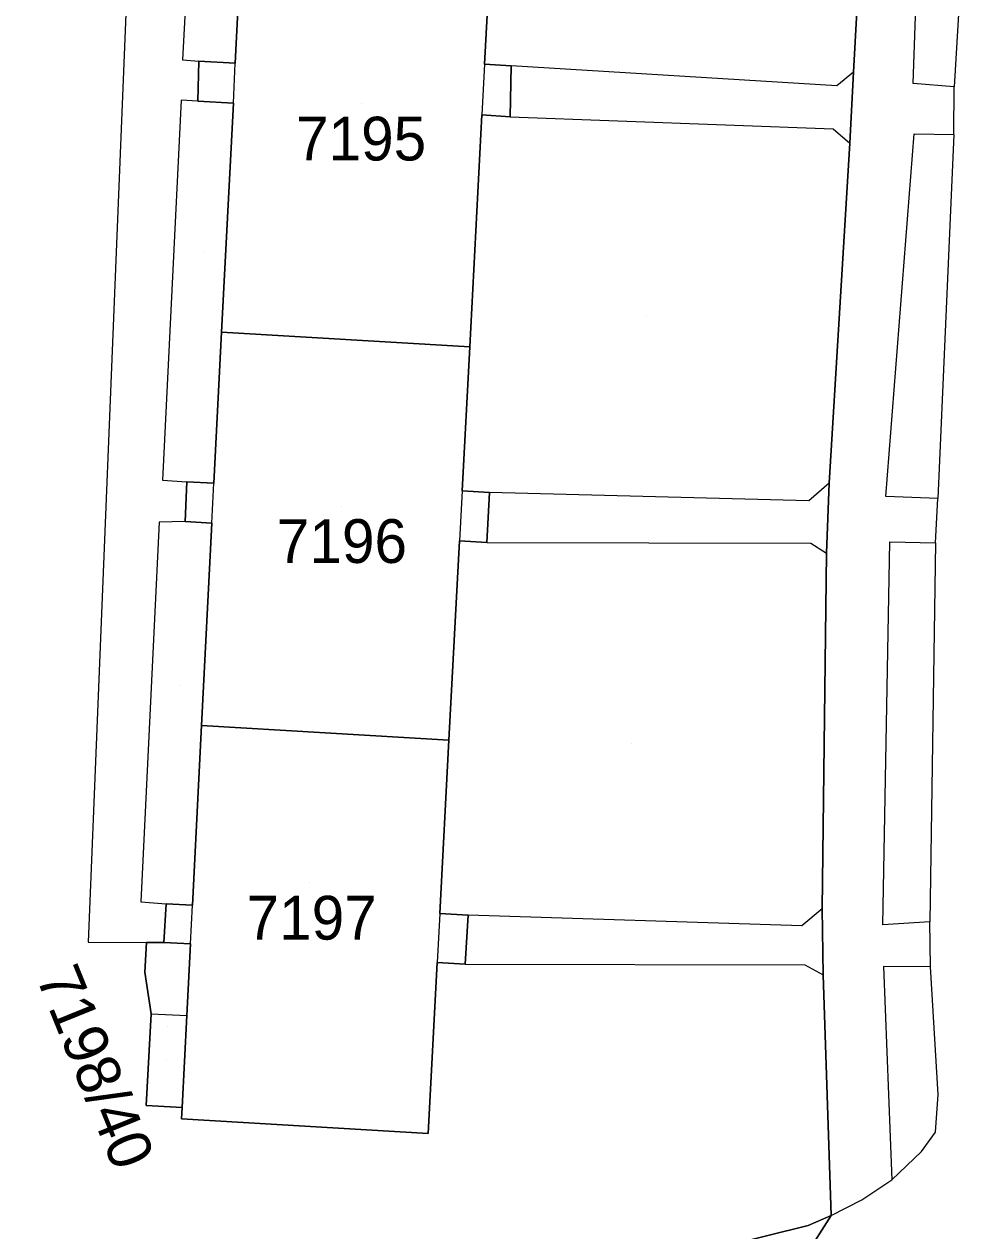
# Model space of a CAD drawing. Extents: x -266199 to -261993, y -1239047 to -1235108.
# Drawn here: x -263566.8 to -263523.4, y -1236600.9 to -1236545.7 of the extents above; entities that cross this region are included whole.
import ezdxf

# ---------------------------------------------------------------- set-up
doc = ezdxf.new("R2010")
doc.units = 0
for name, color, linetype in [('body_kn', 7, 'Continuous'), ('kladpar_druhypozemkov', 7, 'Continuous'), ('kladpar_hranice', 7, 'Continuous'), ('kladpar_parcelnecisla', 7, 'Continuous'), ('kladpar_plochy', 7, 'Continuous'), ('kladpar_sipky', 7, 'Continuous'), ('zappar_hrandruhpozemk', 7, 'Continuous')]:
    doc.layers.add(name, color=color, linetype=linetype)

msp = doc.modelspace()

# ---------------------------------------------------------------- linework, layer by layer
at = {"layer": 'body_kn'}
for p, q in [((-263559.56, -1236547.35), (-263559.56, -1236547.35)), ((-263558.81, -1236547.41), (-263558.81, -1236547.41)), ((-263557.15, -1236547.51), (-263557.15, -1236547.51)), ((-263545.76, -1236547.55), (-263545.76, -1236547.55)), ((-263545.76, -1236547.55), (-263545.76, -1236547.55)), ((-263544.54, -1236547.62), (-263544.54, -1236547.62)), ((-263528.91, -1236547.91), (-263528.91, -1236547.91)), ((-263528.91, -1236547.91), (-263528.91, -1236547.91)), ((-263529.67, -1236548.54), (-263529.67, -1236548.54)), ((-263526.18, -1236548.44), (-263526.18, -1236548.44)), ((-263526.18, -1236548.44), (-263526.18, -1236548.44)), ((-263524.3, -1236548.58), (-263524.3, -1236548.58)), ((-263559.62, -1236549.19), (-263559.62, -1236549.19)), ((-263558.86, -1236549.24), (-263558.86, -1236549.24)), ((-263558.86, -1236549.24), (-263558.86, -1236549.24)), ((-263557.24, -1236549.33), (-263557.24, -1236549.33)), ((-263557.24, -1236549.33), (-263557.24, -1236549.33)), ((-263545.88, -1236549.87), (-263545.88, -1236549.87)), ((-263544.59, -1236549.95), (-263544.59, -1236549.95)), ((-263544.59, -1236549.95), (-263544.59, -1236549.95)), ((-263529.84, -1236550.5), (-263529.84, -1236550.5)), ((-263529.07, -1236551.16), (-263529.07, -1236551.16)), ((-263526.13, -1236550.74), (-263526.13, -1236550.74)), ((-263524.32, -1236550.77), (-263524.32, -1236550.77)), ((-263524.32, -1236550.77), (-263524.32, -1236550.77)), ((-263557.78, -1236559.79), (-263557.78, -1236559.79)), ((-263557.78, -1236559.79), (-263557.78, -1236559.79)), ((-263546.44, -1236560.46), (-263546.44, -1236560.46)), ((-263546.44, -1236560.46), (-263546.44, -1236560.46)), ((-263560.47, -1236566.56), (-263560.47, -1236566.56)), ((-263559.36, -1236566.63), (-263559.36, -1236566.63)), ((-263558.13, -1236566.7), (-263558.13, -1236566.7)), ((-263546.79, -1236567.04), (-263546.79, -1236567.04)), ((-263546.79, -1236567.04), (-263546.79, -1236567.04)), ((-263545.53, -1236567.12), (-263545.53, -1236567.12)), ((-263530.01, -1236566.7), (-263530.01, -1236566.7)), ((-263530.01, -1236566.7), (-263530.01, -1236566.7)), ((-263530.95, -1236567.5), (-263530.95, -1236567.5)), ((-263527.43, -1236567.3), (-263527.43, -1236567.3)), ((-263527.43, -1236567.3), (-263527.43, -1236567.3)), ((-263525.05, -1236567.39), (-263525.05, -1236567.39)), ((-263560.63, -1236568.48), (-263560.63, -1236568.48)), ((-263559.44, -1236568.45), (-263559.44, -1236568.45)), ((-263559.44, -1236568.45), (-263559.44, -1236568.45)), ((-263558.22, -1236568.52), (-263558.22, -1236568.52)), ((-263558.22, -1236568.52), (-263558.22, -1236568.52)), ((-263546.91, -1236569.33), (-263546.91, -1236569.33)), ((-263527.24, -1236569.37), (-263527.24, -1236569.37)), ((-263545.66, -1236569.41), (-263545.66, -1236569.41)), ((-263545.66, -1236569.41), (-263545.66, -1236569.41)), ((-263530.85, -1236569.44), (-263530.85, -1236569.44)), ((-263530.13, -1236569.9), (-263530.13, -1236569.9)), ((-263525.15, -1236569.42), (-263525.15, -1236569.42)), ((-263525.15, -1236569.42), (-263525.15, -1236569.42)), ((-263558.69, -1236577.76), (-263558.69, -1236577.76)), ((-263558.69, -1236577.76), (-263558.69, -1236577.76)), ((-263547.39, -1236578.44), (-263547.39, -1236578.44)), ((-263547.39, -1236578.44), (-263547.39, -1236578.44)), ((-263561.46, -1236585.82), (-263561.46, -1236585.82)), ((-263560.31, -1236585.91), (-263560.31, -1236585.91)), ((-263559.11, -1236585.98), (-263559.11, -1236585.98)), ((-263547.81, -1236586.36), (-263547.81, -1236586.36)), ((-263547.81, -1236586.36), (-263547.81, -1236586.36)), ((-263546.51, -1236586.44), (-263546.51, -1236586.44)), ((-263530.33, -1236586.15), (-263530.33, -1236586.15)), ((-263530.33, -1236586.15), (-263530.33, -1236586.15)), ((-263531.26, -1236586.92), (-263531.26, -1236586.92)), ((-263527.56, -1236586.88), (-263527.56, -1236586.88)), ((-263527.56, -1236586.88), (-263527.56, -1236586.88)), ((-263525.42, -1236586.74), (-263525.42, -1236586.74)), ((-263563.87, -1236587.67), (-263563.87, -1236587.67)), ((-263561.2, -1236587.68), (-263561.2, -1236587.68)), ((-263561.2, -1236587.68), (-263561.2, -1236587.68)), ((-263560.41, -1236587.68), (-263560.41, -1236587.68)), ((-263559.2, -1236587.75), (-263559.2, -1236587.75)), ((-263559.2, -1236587.75), (-263559.2, -1236587.75)), ((-263547.93, -1236588.6), (-263547.93, -1236588.6)), ((-263561.29, -1236589.04), (-263561.29, -1236589.04)), ((-263546.64, -1236588.68), (-263546.64, -1236588.68)), ((-263546.64, -1236588.68), (-263546.64, -1236588.68)), ((-263531.13, -1236588.71), (-263531.13, -1236588.71)), ((-263530.29, -1236589.16), (-263530.29, -1236589.16)), ((-263527.53, -1236588.78), (-263527.53, -1236588.78)), ((-263525.39, -1236588.79), (-263525.39, -1236588.79)), ((-263525.39, -1236588.79), (-263525.39, -1236588.79)), ((-263561, -1236590.94), (-263561, -1236590.94)), ((-263561, -1236590.94), (-263561, -1236590.94)), ((-263559.37, -1236591.02), (-263559.37, -1236591.02)), ((-263525.04, -1236594.63), (-263525.04, -1236594.63)), ((-263561.22, -1236595.13), (-263561.22, -1236595.13)), ((-263559.58, -1236595.22), (-263559.58, -1236595.22)), ((-263559.61, -1236595.74), (-263559.61, -1236595.74)), ((-263525.15, -1236596.35), (-263525.15, -1236596.35)), ((-263548.34, -1236596.41), (-263548.34, -1236596.41)), ((-263548.34, -1236596.41), (-263548.34, -1236596.41)), ((-263525.8, -1236597.23), (-263525.8, -1236597.23)), ((-263527.16, -1236598.52), (-263527.16, -1236598.52)), ((-263527.16, -1236598.52), (-263527.16, -1236598.52)), ((-263528.53, -1236599.44), (-263528.53, -1236599.44)), ((-263529.92, -1236600.16), (-263529.92, -1236600.16)), ((-263529.92, -1236600.16), (-263529.92, -1236600.16)), ((-263530.98, -1236600.62), (-263530.98, -1236600.62))]:
    msp.add_line(p, q, dxfattribs=at)
at = {"layer": 'kladpar_druhypozemkov'}
for p, q in [((-263551.38, -1236549.35), (-263551.38, -1236549.35)), ((-263558.6, -1236556.16), (-263558.6, -1236556.16)), ((-263538.38, -1236559.05), (-263538.38, -1236559.05)), ((-263552.31, -1236567.74), (-263552.31, -1236567.74)), ((-263559.72, -1236575.94), (-263559.72, -1236575.94)), ((-263539.05, -1236578.6), (-263539.05, -1236578.6)), ((-263553.74, -1236584.95), (-263553.74, -1236584.95)), ((-263560.31, -1236593.01), (-263560.31, -1236593.01))]:
    msp.add_line(p, q, dxfattribs=at)
at = {"layer": 'kladpar_hranice'}
for p, q in [((-263546.44, -1236560.46), (-263557.78, -1236559.79)), ((-263557.78, -1236559.79), (-263546.44, -1236560.46)), ((-263547.39, -1236578.44), (-263558.69, -1236577.76)), ((-263558.69, -1236577.76), (-263547.39, -1236578.44))]:
    msp.add_line(p, q, dxfattribs=at)
for points in [[(-263533.65, -1236606.02), (-263529.92, -1236600.16), (-263530.29, -1236589.16), (-263530.33, -1236586.15), (-263530.13, -1236569.9), (-263530.01, -1236566.7), (-263529.07, -1236551.16), (-263528.91, -1236547.91), (-263528.13, -1236533.75), (-263527.74, -1236530.38), (-263527.03, -1236513.3), (-263526.69, -1236510.66), (-263525.84, -1236494.32), (-263525.8, -1236491.06), (-263525.16, -1236480.27), (-263525.13, -1236478.12), (-263525.44, -1236474.41), (-263524.5, -1236462.92)], [(-263528.13, -1236533.75), (-263528.91, -1236547.91), (-263529.07, -1236551.16), (-263530.01, -1236566.7), (-263530.13, -1236569.9), (-263530.33, -1236586.15), (-263530.29, -1236589.16), (-263529.92, -1236600.16), (-263530.98, -1236600.62), (-263601.55, -1236618.12)], [(-263556.86, -1236541.81), (-263557.15, -1236547.51), (-263558.81, -1236547.41), (-263558.86, -1236549.24), (-263557.24, -1236549.33), (-263557.78, -1236559.79), (-263558.13, -1236566.7), (-263559.36, -1236566.63), (-263559.44, -1236568.45), (-263558.22, -1236568.52), (-263558.69, -1236577.76), (-263559.11, -1236585.98), (-263560.31, -1236585.91), (-263560.41, -1236587.68), (-263561.2, -1236587.68), (-263561.29, -1236589.04), (-263561, -1236590.94), (-263561.22, -1236595.13), (-263559.58, -1236595.22), (-263559.61, -1236595.74), (-263548.34, -1236596.41), (-263547.93, -1236588.6), (-263546.64, -1236588.68), (-263546.51, -1236586.44), (-263547.81, -1236586.36), (-263547.39, -1236578.44), (-263546.91, -1236569.33), (-263545.66, -1236569.41), (-263545.53, -1236567.12), (-263546.79, -1236567.04), (-263546.44, -1236560.46), (-263545.88, -1236549.87), (-263544.59, -1236549.95), (-263544.54, -1236547.62), (-263545.76, -1236547.55), (-263545.49, -1236542.49)], [(-263557.78, -1236559.79), (-263557.24, -1236549.33), (-263558.86, -1236549.24), (-263558.81, -1236547.41), (-263557.15, -1236547.51), (-263556.86, -1236541.81)], [(-263545.49, -1236542.49), (-263545.76, -1236547.55), (-263544.54, -1236547.62), (-263544.59, -1236549.95), (-263545.88, -1236549.87), (-263546.44, -1236560.46)], [(-263558.69, -1236577.76), (-263558.22, -1236568.52), (-263559.44, -1236568.45), (-263559.36, -1236566.63), (-263558.13, -1236566.7), (-263557.78, -1236559.79)], [(-263546.44, -1236560.46), (-263546.79, -1236567.04), (-263545.53, -1236567.12), (-263545.66, -1236569.41), (-263546.91, -1236569.33), (-263547.39, -1236578.44)], [(-263548.34, -1236596.41), (-263559.61, -1236595.74), (-263559.58, -1236595.22), (-263559.37, -1236591.02), (-263559.2, -1236587.75), (-263560.41, -1236587.68), (-263560.31, -1236585.91), (-263559.11, -1236585.98), (-263558.69, -1236577.76)], [(-263547.39, -1236578.44), (-263547.81, -1236586.36), (-263546.51, -1236586.44), (-263546.64, -1236588.68), (-263547.93, -1236588.6), (-263548.34, -1236596.41)], [(-263561.2, -1236587.68), (-263560.41, -1236587.68), (-263559.2, -1236587.75), (-263559.37, -1236591.02), (-263559.58, -1236595.22), (-263561.22, -1236595.13), (-263561, -1236590.94), (-263561.29, -1236589.04), (-263561.2, -1236587.68)], [(-263601.55, -1236618.12), (-263530.98, -1236600.62), (-263529.92, -1236600.16), (-263533.65, -1236606.02)]]:
    msp.add_lwpolyline(points, dxfattribs=at)
at = {"layer": 'kladpar_plochy'}
for p, q in [((-263528.13, -1236533.75), (-263528.91, -1236547.91)), ((-263556.86, -1236541.81), (-263557.15, -1236547.51)), ((-263545.76, -1236547.55), (-263545.49, -1236542.49)), ((-263558.81, -1236547.41), (-263558.86, -1236549.24)), ((-263557.15, -1236547.51), (-263558.81, -1236547.41)), ((-263544.54, -1236547.62), (-263545.76, -1236547.55)), ((-263544.59, -1236549.95), (-263544.54, -1236547.62)), ((-263528.91, -1236547.91), (-263529.07, -1236551.16)), ((-263558.86, -1236549.24), (-263557.24, -1236549.33)), ((-263557.24, -1236549.33), (-263557.78, -1236559.79)), ((-263546.44, -1236560.46), (-263545.88, -1236549.87)), ((-263545.88, -1236549.87), (-263544.59, -1236549.95)), ((-263529.07, -1236551.16), (-263530.01, -1236566.7)), ((-263557.78, -1236559.79), (-263558.13, -1236566.7)), ((-263546.79, -1236567.04), (-263546.44, -1236560.46)), ((-263559.36, -1236566.63), (-263559.44, -1236568.45)), ((-263558.13, -1236566.7), (-263559.36, -1236566.63)), ((-263545.53, -1236567.12), (-263546.79, -1236567.04)), ((-263545.66, -1236569.41), (-263545.53, -1236567.12)), ((-263530.01, -1236566.7), (-263530.13, -1236569.9)), ((-263559.44, -1236568.45), (-263558.22, -1236568.52)), ((-263558.22, -1236568.52), (-263558.69, -1236577.76)), ((-263547.39, -1236578.44), (-263546.91, -1236569.33)), ((-263546.91, -1236569.33), (-263545.66, -1236569.41)), ((-263530.13, -1236569.9), (-263530.33, -1236586.15)), ((-263558.69, -1236577.76), (-263559.11, -1236585.98)), ((-263547.81, -1236586.36), (-263547.39, -1236578.44)), ((-263560.31, -1236585.91), (-263560.41, -1236587.68)), ((-263559.11, -1236585.98), (-263560.31, -1236585.91)), ((-263546.51, -1236586.44), (-263547.81, -1236586.36)), ((-263546.64, -1236588.68), (-263546.51, -1236586.44)), ((-263530.33, -1236586.15), (-263530.29, -1236589.16)), ((-263561.2, -1236587.68), (-263561.29, -1236589.04)), ((-263560.41, -1236587.68), (-263561.2, -1236587.68)), ((-263548.34, -1236596.41), (-263547.93, -1236588.6)), ((-263547.93, -1236588.6), (-263546.64, -1236588.68)), ((-263561.29, -1236589.04), (-263561, -1236590.94)), ((-263530.29, -1236589.16), (-263529.92, -1236600.16)), ((-263561, -1236590.94), (-263561.22, -1236595.13)), ((-263561.22, -1236595.13), (-263559.58, -1236595.22)), ((-263559.58, -1236595.22), (-263559.61, -1236595.74)), ((-263559.61, -1236595.74), (-263548.34, -1236596.41)), ((-263529.92, -1236600.16), (-263530.98, -1236600.62)), ((-263530.98, -1236600.62), (-263601.55, -1236618.12))]:
    msp.add_line(p, q, dxfattribs=at)
for points in [[(-263533.65, -1236606.02), (-263529.92, -1236600.16), (-263530.29, -1236589.16), (-263530.33, -1236586.15), (-263530.13, -1236569.9), (-263530.01, -1236566.7), (-263529.07, -1236551.16), (-263528.91, -1236547.91), (-263528.13, -1236533.75), (-263527.74, -1236530.38), (-263527.03, -1236513.3), (-263526.69, -1236510.66), (-263525.84, -1236494.32), (-263525.8, -1236491.06), (-263525.16, -1236480.27), (-263525.13, -1236478.12), (-263525.44, -1236474.41), (-263524.5, -1236462.92)], [(-263601.55, -1236618.12), (-263530.98, -1236600.62), (-263529.92, -1236600.16), (-263533.65, -1236606.02)]]:
    msp.add_lwpolyline(points, dxfattribs=at)
for points in [[(-263557.78, -1236559.79), (-263557.24, -1236549.33), (-263558.86, -1236549.24), (-263558.81, -1236547.41), (-263557.15, -1236547.51), (-263556.86, -1236541.81), (-263545.49, -1236542.49), (-263545.76, -1236547.55), (-263544.54, -1236547.62), (-263544.59, -1236549.95), (-263545.88, -1236549.87), (-263546.44, -1236560.46)], [(-263558.69, -1236577.76), (-263558.22, -1236568.52), (-263559.44, -1236568.45), (-263559.36, -1236566.63), (-263558.13, -1236566.7), (-263557.78, -1236559.79), (-263546.44, -1236560.46), (-263546.79, -1236567.04), (-263545.53, -1236567.12), (-263545.66, -1236569.41), (-263546.91, -1236569.33), (-263547.39, -1236578.44)], [(-263548.34, -1236596.41), (-263559.61, -1236595.74), (-263559.58, -1236595.22), (-263559.37, -1236591.02), (-263559.2, -1236587.75), (-263560.41, -1236587.68), (-263560.31, -1236585.91), (-263559.11, -1236585.98), (-263558.69, -1236577.76), (-263547.39, -1236578.44), (-263547.81, -1236586.36), (-263546.51, -1236586.44), (-263546.64, -1236588.68), (-263547.93, -1236588.6)], [(-263561.2, -1236587.68), (-263560.41, -1236587.68), (-263559.2, -1236587.75), (-263559.37, -1236591.02), (-263559.58, -1236595.22), (-263561.22, -1236595.13), (-263561, -1236590.94), (-263561.29, -1236589.04)]]:
    msp.add_lwpolyline(points, close=True, dxfattribs=at)
at = {"layer": 'kladpar_sipky'}
msp.add_line((-263560.25, -1236591.54), (-263560.25, -1236591.54), dxfattribs=at)
at = {"layer": 'zappar_hrandruhpozemk'}
for p, q in [((-263558.72, -1236531.55), (-263559.56, -1236547.35)), ((-263561.61, -1236532), (-263563.87, -1236587.67)), ((-263523.45, -1236533.66), (-263524.3, -1236548.58)), ((-263559.56, -1236547.35), (-263558.81, -1236547.41)), ((-263557.24, -1236549.33), (-263557.15, -1236547.51)), ((-263545.76, -1236547.55), (-263545.88, -1236549.87)), ((-263529.67, -1236548.54), (-263544.54, -1236547.62)), ((-263528.91, -1236547.91), (-263529.67, -1236548.54)), ((-263559.62, -1236549.19), (-263560.47, -1236566.56)), ((-263558.86, -1236549.24), (-263559.62, -1236549.19)), ((-263544.59, -1236549.95), (-263529.84, -1236550.5)), ((-263529.84, -1236550.5), (-263529.07, -1236551.16)), ((-263527.43, -1236567.3), (-263526.13, -1236550.74)), ((-263526.13, -1236550.74), (-263524.32, -1236550.77)), ((-263524.32, -1236550.77), (-263525.05, -1236567.39)), ((-263560.47, -1236566.56), (-263559.36, -1236566.63)), ((-263558.22, -1236568.52), (-263558.13, -1236566.7)), ((-263546.79, -1236567.04), (-263546.91, -1236569.33)), ((-263530.95, -1236567.5), (-263545.53, -1236567.12)), ((-263530.01, -1236566.7), (-263530.95, -1236567.5)), ((-263560.63, -1236568.48), (-263561.46, -1236585.82)), ((-263559.44, -1236568.45), (-263560.63, -1236568.48)), ((-263545.66, -1236569.41), (-263530.85, -1236569.44)), ((-263530.85, -1236569.44), (-263530.13, -1236569.9)), ((-263525.15, -1236569.42), (-263525.42, -1236586.74)), ((-263561.46, -1236585.82), (-263560.31, -1236585.91)), ((-263559.2, -1236587.75), (-263559.11, -1236585.98)), ((-263547.81, -1236586.36), (-263547.93, -1236588.6)), ((-263531.26, -1236586.92), (-263546.51, -1236586.44)), ((-263530.33, -1236586.15), (-263531.26, -1236586.92)), ((-263563.87, -1236587.67), (-263561.2, -1236587.68)), ((-263546.64, -1236588.68), (-263531.13, -1236588.71)), ((-263531.13, -1236588.71), (-263530.29, -1236589.16)), ((-263525.04, -1236594.63), (-263525.39, -1236588.79)), ((-263561, -1236590.94), (-263559.37, -1236591.02))]:
    msp.add_line(p, q, dxfattribs=at)
for points in [[(-263526.18, -1236548.44), (-263525.66, -1236533.47), (-263523.45, -1236533.66)], [(-263524.32, -1236550.77), (-263524.3, -1236548.58), (-263526.18, -1236548.44)], [(-263525.15, -1236569.42), (-263525.05, -1236567.39), (-263527.43, -1236567.3)], [(-263527.56, -1236586.88), (-263527.24, -1236569.37), (-263525.15, -1236569.42)], [(-263525.39, -1236588.79), (-263525.42, -1236586.74), (-263527.56, -1236586.88)], [(-263525.39, -1236588.79), (-263527.53, -1236588.78), (-263527.16, -1236598.52)], [(-263527.16, -1236598.52), (-263525.8, -1236597.23), (-263525.15, -1236596.35), (-263525.04, -1236594.63)], [(-263529.92, -1236600.16), (-263528.53, -1236599.44), (-263527.16, -1236598.52)]]:
    msp.add_lwpolyline(points, dxfattribs=at)

# ---------------------------------------------------------------- texts
at = {"layer": 'kladpar_parcelnecisla'}
for s, p in [('7195', (-263554.378, -1236551.95)), ('7196', (-263555.253, -1236570.34)), ('7197', (-263556.636, -1236587.55))]:
    msp.add_text(s, height=2, dxfattribs=at).set_placement(p)
msp.add_text('7198/40', height=2, rotation=292, dxfattribs=at).set_placement((-263566.27, -1236589.251))

doc.saveas('drawing.dxf')
